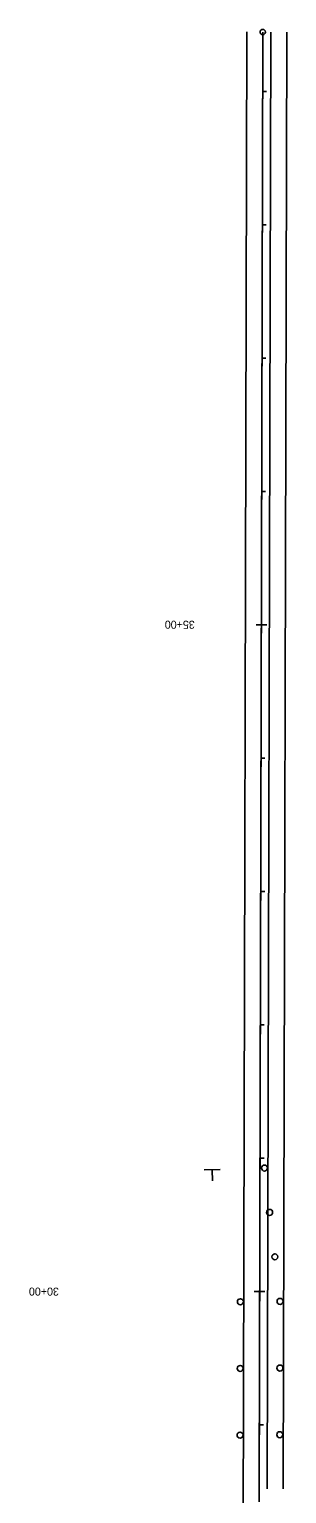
# Model space of a CAD drawing. Extents: x 1665984 to 1683035, y 227404 to 233856.
# Drawn here: x 1677130 to 1677324, y 232758 to 233856 of the extents above; entities that cross this region are included whole.
import ezdxf

# ---------------------------------------------------------------- set-up
doc = ezdxf.new("R2010")
doc.units = 0
for name, color, linetype in [('Default', 7, 'Continuous'), ('Level 47', 7, 'Continuous'), ('R_Horz Alg', 7, 'Continuous'), ('R_Horz Alg Annot', 7, 'Continuous'), ('S_EDGE_PAVEMENT', 7, 'Continuous')]:
    doc.layers.add(name, color=color, linetype=linetype)

msp = doc.modelspace()

# ---------------------------------------------------------------- linework, layer by layer
at = {"layer": 'Default'}
for p, q in [((1677261.8, 233000.5), (1677273.7, 233000.7)), ((1677267.7, 233000.5), (1677267.9, 232992.4))]:
    msp.add_line(p, q, dxfattribs=at)
at = {"layer": 'Level 47'}
for centre in [(1677307, 233001.9), (1677310.9, 232968.6), (1677314.8, 232935.3), (1677288.9, 232901.6), (1677318.7, 232901.9), (1677288.8, 232851.6), (1677318.6, 232851.9), (1677288.7, 232801.6), (1677318.5, 232801.9)]:
    msp.add_circle(centre, 2.25, dxfattribs=at)
at = {"layer": 'R_Horz Alg'}
msp.add_line((1677303.1, 232751.6), (1677305.7, 233853.8), dxfattribs=at)
at = {"layer": 'R_Horz Alg Annot'}
for points in [[(1677308.6, 233809.2), (1677305.6, 233809.2)], [(1677308.4, 233709.2), (1677305.4, 233709.2)], [(1677308.1, 233609.2), (1677305.1, 233609.2)], [(1677307.9, 233509.2), (1677304.9, 233509.2)], [(1677300.7, 233409.2), (1677308.7, 233409.2)], [(1677307.4, 233309.2), (1677304.4, 233309.2)], [(1677307.2, 233209.2), (1677304.2, 233209.2)], [(1677306.9, 233109.2), (1677303.9, 233109.2)], [(1677306.7, 233009.2), (1677303.7, 233009.2)], [(1677299.4, 232909.2), (1677307.4, 232909.2)], [(1677306.2, 232809.2), (1677303.2, 232809.2)]]:
    msp.add_lwpolyline(points, dxfattribs=at)
msp.add_circle((1677305.7, 233853.8), 2, dxfattribs=at)
at = {"layer": 'S_EDGE_PAVEMENT'}
for p, q in [((1677293.7, 233853.9), (1677291, 232703.6)), ((1677305.7, 233853.8), (1677303.1, 232761.2)), ((1677311.7, 233853.8), (1677309.1, 232761.2)), ((1677323.7, 233853.8), (1677321.1, 232761.2))]:
    msp.add_line(p, q, dxfattribs=at)

# ---------------------------------------------------------------- texts
at = {"layer": 'R_Horz Alg Annot'}
for s, p in [('35+00', (1677254.7, 233412.3)), ('30+00', (1677152.7, 232912.2))]:
    msp.add_text(s, height=6, rotation=179.8615, dxfattribs=at).set_placement(p)

doc.saveas('drawing.dxf')
